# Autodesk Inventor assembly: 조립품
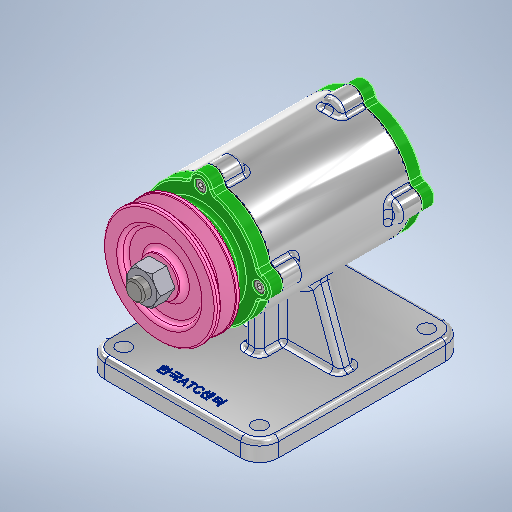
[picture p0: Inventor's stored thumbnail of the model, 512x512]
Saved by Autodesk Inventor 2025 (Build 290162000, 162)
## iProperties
Created: 2024-08
Part Number: 조립품
Document SubType Name: Assembly
Designer: samsung
Author: samsung
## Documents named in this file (12)
- C:\Users\samsung\Desktop\740807V1006\조립품.iam
- C:\Users\samsung\Desktop\740807V1006\본체.ipt
- C:\Users\samsung\Desktop\740807V1006\베어링 6204\베어링 6204.ipt
- C:\Users\samsung\Desktop\740807V1006\뒤커버\뒤커버.ipt
- C:\Users\samsung\Desktop\740807V1006\축\축.ipt
- C:\Users\samsung\Desktop\740807V1006\볼트 M4 x 12\볼트 M4 x 12.ipt
- C:\Users\samsung\Desktop\740807V1006\앞커버\앞커버.ipt
- C:\Users\samsung\Desktop\740807V1006\오일실\오일실.ipt
- C:\Users\samsung\Desktop\740807V1006\키 4 x 4\키 4 x 4.ipt
- C:\Users\samsung\Desktop\740807V1006\V-벨트풀리\V-벨트풀리.ipt
- C:\Users\samsung\Desktop\740807V1006\너트 M12 x 1.25\너트 M12 x 1.25.ipt
- C:\Users\samsung\Desktop\740807V1006\개스킷\개스킷.ipt
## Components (3 placed, 2 different names)
1. V-벨트풀리:1 — 각도:4
2. 개스킷:1
3. 개스킷:2
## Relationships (1: Angle 1)
- 각도:4 [Angle]: V-벨트풀리:1
